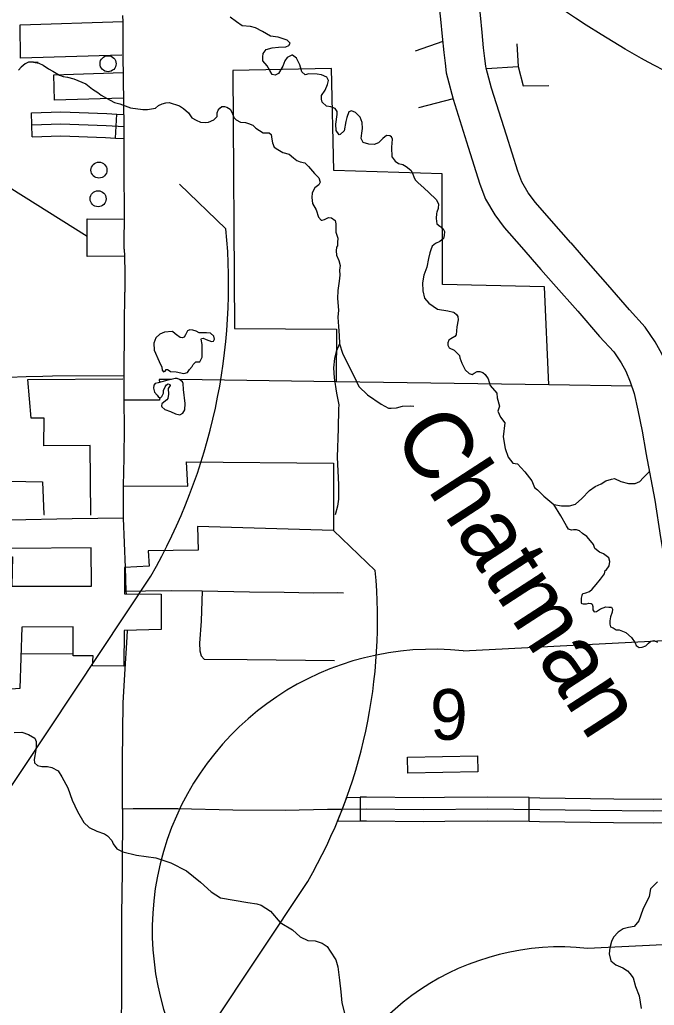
# Model space of a CAD drawing. Extents: x 22866 to 28196, y 1324810 to 1328105.
# Drawn here: x 25825.7 to 25920.9, y 1325934.5 to 1326082.4 of the extents above; entities that cross this region are included whole.
import ezdxf

# ---------------------------------------------------------------- set-up
doc = ezdxf.new("R2010")
doc.units = 0
for name, color, linetype in [('Level 10', 7, 'Continuous'), ('Level 31', 7, 'Continuous'), ('Level 32', 7, 'Continuous'), ('Level 33', 7, 'Continuous'), ('Level 35', 7, 'Continuous'), ('Level 5', 7, 'Continuous'), ('Level 56', 7, 'Continuous'), ('Level 6', 7, 'Continuous'), ('Level 63', 7, 'Continuous')]:
    doc.layers.add(name, color=color, linetype=linetype)

msp = doc.modelspace()

# ---------------------------------------------------------------- linework, layer by layer
at = {"layer": 'Level 10'}
for points in [[(25895.05, 1326080.47), (25894.8, 1326083.11), (25894.15, 1326088.91), (25893.68, 1326091.57)], [(25887.77, 1326090.53), (25888.21, 1326088.05), (25888.83, 1326082.49), (25889.08, 1326079.91)], [(25889.08, 1326079.91), (25889.31, 1326077.49), (25889.52, 1326075.88), (25889.67, 1326074.45), (25889.84, 1326073.68), (25890.71, 1326070.47), (25892.98, 1326063.3), (25894.73, 1326057.73), (25895.58, 1326055.48), (25896.94, 1326053.13), (25898.37, 1326051.22), (25900.96, 1326048.25), (25903.88, 1326044.94)], [(25908.38, 1326048.91), (25905.47, 1326052.21), (25903.04, 1326055), (25901.96, 1326056.44), (25901.02, 1326058.06), (25900.4, 1326059.69), (25898.7, 1326065.1), (25896.47, 1326072.16), (25895.67, 1326075.13), (25895.6, 1326075.44), (25895.48, 1326076.6), (25895.27, 1326078.17), (25895.05, 1326080.47)], [(25925.53, 1326018.46), (25924.97, 1326021.79), (25924.28, 1326025.05), (25923.67, 1326027.88), (25922.9, 1326030.2), (25922, 1326032.28), (25921.03, 1326034.05), (25919.52, 1326036.28), (25917.16, 1326038.87), (25913.93, 1326042.62), (25910.26, 1326046.76), (25908.39, 1326048.9)], [(25903.87, 1326044.94), (25905.76, 1326042.79), (25909.41, 1326038.67), (25912.67, 1326034.88), (25914.8, 1326032.55), (25915.91, 1326030.91), (25916.6, 1326029.64), (25917.28, 1326028.06), (25917.87, 1326026.3), (25918.41, 1326023.79), (25919.07, 1326020.67), (25919.61, 1326017.46)], [(25919.62, 1326017.41), (25920.95, 1326010.28), (25921.81, 1326004.72), (25922.47, 1326000.87), (25923.07, 1325997.99), (25924.25, 1325990.17), (25925.03, 1325984.11), (25925.3, 1325981.88), (25931.25, 1325982.7)]]:
    msp.add_lwpolyline(points, dxfattribs=at)
at = {"layer": 'Level 31'}
for p, q in [((25873.34, 1325962.08), (25874.74, 1325965.69)), ((25876.75, 1325965.7), (25876.77, 1325962.1)), ((25902.09, 1325962.05), (25902.12, 1325965.65))]:
    msp.add_line(p, q, dxfattribs=at)
for points in [[(25841.39, 1326046.91), (25841.44, 1326044.37), (25841.44, 1326041.53)], [(25841.39, 1326036.43), (25841.44, 1326041.53)], [(25841.36, 1326028.5), (25841.36, 1326028.97), (25841.39, 1326036.43)], [(25841.36, 1326028.97), (25830.62, 1326028.91), (25829.16, 1326028.87), (25826.66, 1326028.79), (25823.99, 1326028.73)], [(25841.67, 1325996.63), (25841.54, 1326000.2)], [(25841.67, 1325996.63), (25841.38, 1325996.61)], [(25841.67, 1325996.63), (25844.57, 1325996.71), (25848.49, 1325996.76), (25853.07, 1325996.68), (25860.18, 1325996.54), (25865.38, 1325996.47)], [(25841.71, 1325996.24), (25841.67, 1325996.63)], [(25853.07, 1325996.68), (25852.91, 1325992.14), (25852.66, 1325988.86), (25852.73, 1325987.71), (25852.91, 1325986.95), (25853.36, 1325986.43), (25859.82, 1325986.37), (25872.92, 1325986.23)], [(25865.38, 1325996.47), (25869.74, 1325996.4), (25873.38, 1325996.42), (25874.26, 1325996.38)], [(25841.11, 1325963.91), (25841.11, 1325971.2), (25841.22, 1325979.88), (25841.53, 1325984.99), (25841.77, 1325988.9), (25841.84, 1325990.73)], [(25825.88, 1325987.24), (25833.72, 1325987.27)], [(25874.74, 1325965.69), (25876.75, 1325965.7)], [(25889.42, 1325965.66), (25886.26, 1325965.64), (25877.69, 1325965.71), (25876.75, 1325965.7)], [(25902.12, 1325965.65), (25895.89, 1325965.71), (25889.42, 1325965.66)], [(25902.12, 1325965.65), (25903.72, 1325965.64), (25911.33, 1325965.5), (25914.8, 1325965.46)], [(25914.8, 1325965.46), (25920.74, 1325965.4), (25927.25, 1325965.47)], [(25874.07, 1325963.89), (25871.85, 1325963.87), (25865.53, 1325963.7), (25857.66, 1325963.77), (25849.4, 1325963.98), (25842.73, 1325963.98), (25841.11, 1325963.91)], [(25841.11, 1325963.91), (25841.04, 1325954.57), (25840.94, 1325948.06), (25840.94, 1325940.45), (25840.94, 1325936.85), (25840.91, 1325930.85), (25840.94, 1325926.9), (25840.91, 1325921.06)], [(25927.45, 1325963.67), (25920.74, 1325963.6), (25911.3, 1325963.7), (25903.7, 1325963.84), (25895.89, 1325963.91), (25886.26, 1325963.84), (25877.69, 1325963.91), (25874.07, 1325963.89)], [(25876.77, 1325962.1), (25873.34, 1325962.08)], [(25889.45, 1325962.06), (25886.26, 1325962.04), (25877.69, 1325962.11), (25876.77, 1325962.1)], [(25902.09, 1325962.05), (25895.89, 1325962.11), (25889.45, 1325962.06)], [(25914.76, 1325961.86), (25911.28, 1325961.9), (25903.67, 1325962.04), (25902.09, 1325962.05)], [(25927.84, 1325961.88), (25920.74, 1325961.8), (25914.76, 1325961.86)]]:
    msp.add_lwpolyline(points, dxfattribs=at)
at = {"layer": 'Level 32'}
for p, q in [((25827.56, 1326064.83), (25827.44, 1326068.43)), ((25840.07, 1326064.65), (25840.26, 1326068.25))]:
    msp.add_line(p, q, dxfattribs=at)
for points in [[(25827.44, 1326068.43), (25831.86, 1326068.57), (25838.74, 1326068.33), (25840.26, 1326068.25)], [(25840.26, 1326068.25), (25841.35, 1326068.19)], [(25827.5, 1326066.63), (25831.86, 1326066.77), (25838.66, 1326066.53), (25841.38, 1326066.39)], [(25827.56, 1326064.83), (25831.86, 1326064.97), (25838.58, 1326064.73), (25840.07, 1326064.65)], [(25840.07, 1326064.65), (25841.29, 1326064.59)]]:
    msp.add_lwpolyline(points, dxfattribs=at)
at = {"layer": 'Level 33'}
for points in [[(25910.68, 1326081.61), (25909.05, 1326082.66), (25907.69, 1326083.55), (25906.83, 1326084.36), (25905.86, 1326085.46), (25904.81, 1326086.82), (25903.74, 1326088.05), (25902.96, 1326088.91), (25902.07, 1326089.59), (25901.26, 1326090.06), (25900.32, 1326090.64), (25899.51, 1326091.11)], [(25841.21, 1326077.16), (25841.2, 1326082.07), (25841.17, 1326083.02)], [(25953.2, 1326070.87), (25945.13, 1326070.88), (25938.31, 1326070.9), (25936.09, 1326070.95), (25932.09, 1326071.31), (25928.56, 1326071.94), (25927.7, 1326072.15), (25925.88, 1326073.01), (25923.23, 1326074.32), (25919.98, 1326076.04), (25918.96, 1326076.57), (25916.5, 1326078), (25912.93, 1326080.21), (25910.68, 1326081.61)], [(25889.15, 1326079.16), (25885, 1326077.69)], [(25900.24, 1326078.77), (25900.48, 1326075.38), (25901.23, 1326072.5), (25905.08, 1326072.54)], [(25841.37, 1326047.99), (25841.39, 1326053.83), (25841.35, 1326059.21), (25841.38, 1326066.39), (25841.21, 1326077.16)], [(25895.69, 1326075.07), (25900.48, 1326075.38)], [(25890.69, 1326070.56), (25885.52, 1326069.2)], [(25841.37, 1326047.99), (25841.39, 1326046.91)], [(25841.39, 1326021.16), (25841.37, 1326025.27), (25841.36, 1326028.5)], [(25841.27, 1326012.45), (25841.34, 1326016.65), (25841.39, 1326021.16)], [(25841.24, 1326007.61), (25841.27, 1326012.45)], [(25841.24, 1326007.61), (25833.55, 1326007.52), (25824.33, 1326007.28)], [(25841.54, 1326000.2), (25841.24, 1326007.61)]]:
    msp.add_lwpolyline(points, dxfattribs=at)
at = {"layer": 'Level 35'}
for points in [[(25869.06, 1326074.31), (25868.49, 1326074.13), (25868.02, 1326074.6), (25867.7, 1326075.65), (25867.23, 1326076.64), (25866.6, 1326077.11), (25866.5, 1326077.11), (25865.82, 1326076.75), (25865.45, 1326076.23), (25865.14, 1326075.44), (25864.51, 1326074.34), (25863.99, 1326074.08), (25863.57, 1326074.18), (25863.21, 1326074.81), (25862.79, 1326075.49), (25862.16, 1326076.23), (25862.16, 1326076.85), (25862.21, 1326077.32), (25862.68, 1326077.95), (25863.57, 1326078.21), (25864.51, 1326078.27), (25865.61, 1326078.32), (25866.08, 1326078.53), (25866.24, 1326078.89), (25865.82, 1326079.36), (25864.46, 1326079.78), (25863.31, 1326079.94), (25862.11, 1326080.62), (25861.06, 1326081.2), (25860.33, 1326081.41), (25859.08, 1326081.51), (25858.19, 1326082.09), (25857.25, 1326082.77)], [(25828.44, 1326075.98), (25827.76, 1326076.03), (25827.03, 1326076.06), (25826.51, 1326075.77), (25825.93, 1326075.27), (25825.49, 1326074.86)], [(25827.76, 1326076.03), (25828.57, 1326075.9), (25829.19, 1326075.61), (25830, 1326075.04), (25830.68, 1326074.67), (25831.65, 1326074.1), (25832.22, 1326073.89), (25832.88, 1326073.78), (25833.81, 1326073.55), (25835.59, 1326072.79), (25836.61, 1326072), (25837.39, 1326071.48), (25837.92, 1326071.09), (25838.7, 1326070.64), (25839.9, 1326069.99), (25840.71, 1326069.81)], [(25871.99, 1326073.29), (25871.78, 1326073.77), (25870.94, 1326074.13), (25870.32, 1326074.24), (25869.06, 1326074.31)], [(25881.56, 1326061.78), (25881.5, 1326063.3), (25881.61, 1326064.5), (25881.45, 1326064.82), (25881.19, 1326064.98), (25880.72, 1326065.03), (25880.14, 1326064.56), (25879.52, 1326063.93), (25878.84, 1326063.67), (25878.05, 1326063.72), (25877.22, 1326063.98), (25876.9, 1326064.56), (25877.01, 1326065.39), (25877.11, 1326066.07), (25877.06, 1326066.96), (25876.75, 1326067.8), (25876.07, 1326068.48), (25875.44, 1326068.74), (25875.07, 1326068.59), (25874.76, 1326067.75), (25874.6, 1326067.12), (25874.34, 1326065.71), (25873.77, 1326065.18), (25873.61, 1326065.13), (25873.14, 1326065.76), (25873.09, 1326066.75), (25873.3, 1326068.17), (25873.3, 1326068.64), (25873.03, 1326069.06), (25872.35, 1326069.32), (25871.73, 1326069.42), (25871.05, 1326070.05), (25870.94, 1326070.47), (25870.94, 1326071.04), (25871.52, 1326071.83), (25871.88, 1326072.67), (25871.99, 1326073.29)], [(25840.71, 1326069.81), (25842.31, 1326069.18), (25844.14, 1326068.92), (25844.87, 1326068.94), (25846.07, 1326069.15), (25846.52, 1326069.55), (25847.07, 1326069.81), (25847.59, 1326069.96), (25848.11, 1326069.99), (25849.65, 1326069.47), (25850.25, 1326069.08), (25851.03, 1326068.43), (25851.53, 1326067.67), (25852.16, 1326067.33), (25852.81, 1326067.02), (25853.6, 1326066.96), (25854.01, 1326067.04), (25854.82, 1326067.36), (25855.29, 1326067.9), (25855.32, 1326068.43), (25855.45, 1326068.82), (25855.69, 1326069.16), (25856, 1326069.37), (25856.42, 1326069.4), (25856.78, 1326069.29), (25857.25, 1326068.98), (25857.54, 1326068.43), (25857.8, 1326067.75), (25858.14, 1326067.36), (25858.8, 1326067.04), (25859.55, 1326066.96), (25860, 1326066.81), (25860.65, 1326066.6), (25861.1, 1326066.13), (25862.22, 1326065.42), (25862.74, 1326065.45), (25863.11, 1326065.45), (25863.42, 1326065.18), (25863.5, 1326064.5), (25863.63, 1326063.95), (25863.87, 1326063.27), (25864.39, 1326062.91), (25865.17, 1326062.49), (25866.09, 1326062.25), (25866.77, 1326061.7), (25867.27, 1326061.29), (25867.76, 1326061.08), (25868.44, 1326060.92), (25869.02, 1326060.4), (25869.93, 1326059.35)], [(25881.56, 1326061.78), (25882.03, 1326061.18), (25882.53, 1326060.82), (25883.16, 1326060.68), (25883.68, 1326060.4), (25884.36, 1326059.85), (25884.62, 1326059.38), (25884.86, 1326058.67), (25885.07, 1326058.33), (25885.43, 1326057.96), (25886.37, 1326057.15), (25887.05, 1326056.5), (25888.18, 1326055.43), (25888.49, 1326054.8), (25888.44, 1326054.09), (25888.28, 1326053.52), (25888.23, 1326053.31), (25888.18, 1326052.6), (25888.26, 1326051.79), (25888.73, 1326051.42), (25888.99, 1326051.21), (25889.22, 1326051.03), (25889.41, 1326050.61), (25889.38, 1326050.04), (25889.28, 1326049.59), (25888.7, 1326049.11), (25888.05, 1326048.8)], [(25869.93, 1326059.35), (25870.56, 1326058.66), (25870.74, 1326058.05), (25870.56, 1326057.64), (25869.98, 1326057.19), (25869.57, 1326056.41), (25869.49, 1326055.75), (25869.62, 1326054.84), (25870.17, 1326053.89), (25870.51, 1326052.77), (25870.9, 1326052.35), (25871.06, 1326052.33), (25871.4, 1326052.43), (25872.02, 1326052.72), (25872.44, 1326052.69), (25872.99, 1326052.3), (25873.12, 1326051.75), (25873.09, 1326050.52), (25873.41, 1326049.6), (25873.38, 1326048.98), (25873.38, 1326048.45), (25873.23, 1326048.25), (25873.15, 1326047.7), (25873.23, 1326047.08), (25873.54, 1326046.27), (25873.75, 1326045.51), (25873.67, 1326044.83), (25873.72, 1326044.07), (25873.62, 1326043.15), (25873.43, 1326041.79), (25873.36, 1326040.56), (25873.51, 1326038.84), (25873.43, 1326037.79), (25873.49, 1326036.38)], [(25888.05, 1326048.8), (25887.55, 1326048.41), (25887.34, 1326047.88), (25887.21, 1326047.41), (25887.03, 1326046.57), (25886.74, 1326045.29), (25886.32, 1326044.09), (25886.11, 1326042.94), (25886.16, 1326041.73), (25886.4, 1326040.64), (25887.05, 1326039.85), (25888.36, 1326038.96), (25889.93, 1326038.73), (25890.74, 1326038.52), (25890.84, 1326038.49), (25891.21, 1326038.15), (25891.39, 1326037.86), (25891.47, 1326037.39), (25891.26, 1326036.32), (25891.16, 1326035.12)], [(25848.57, 1326035.64), (25847.39, 1326035.51), (25846.69, 1326035.22), (25846.09, 1326034.65), (25845.82, 1326033.84), (25845.88, 1326032.79), (25846.61, 1326031.09), (25847.03, 1326030.25), (25847.08, 1326029.81), (25847.26, 1326029.57), (25847.52, 1326029.68), (25847.68, 1326029.91), (25847.86, 1326029.91), (25847.97, 1326029.86), (25848.33, 1326029.6), (25849.14, 1326029.57), (25850.32, 1326029.31), (25850.84, 1326029.47), (25851.16, 1326029.89), (25851.55, 1326030.38), (25851.73, 1326030.64), (25852.12, 1326031.04), (25852.7, 1326031.06), (25853.06, 1326031.77), (25853.06, 1326033.65), (25852.93, 1326034.44), (25852.96, 1326034.57), (25853.2, 1326034.6), (25853.67, 1326034.41), (25854.45, 1326034.12), (25854.76, 1326034.15), (25854.89, 1326034.44), (25854.79, 1326034.91), (25854.29, 1326035.38), (25853.72, 1326035.43), (25853.06, 1326035.41), (25852.62, 1326035.41), (25852.15, 1326035.69), (25851.65, 1326035.82), (25851.21, 1326035.85), (25850.87, 1326035.72), (25850.58, 1326035.12), (25850.37, 1326034.75), (25850.06, 1326034.65), (25849.75, 1326034.73), (25849.2, 1326035.14), (25849.01, 1326035.25), (25848.59, 1326035.64)], [(25873.49, 1326036.38), (25873.62, 1326035.04), (25873.64, 1326033.78), (25874.11, 1326032.37), (25875.16, 1326030.22), (25875.89, 1326028.76), (25876.57, 1326027.37), (25877.85, 1326026.09), (25879.92, 1326024.7), (25880.99, 1326024.1), (25881.43, 1326024.1), (25882.22, 1326024.15), (25883.13, 1326024.42), (25884.33, 1326024.45), (25884.79, 1326024.43)], [(25891.16, 1326035.12), (25890.97, 1326034.87), (25890.37, 1326034.53), (25890.06, 1326034.29), (25889.93, 1326033.93), (25889.9, 1326033.58), (25890.13, 1326033.17), (25890.84, 1326032.83), (25891.65, 1326032.02), (25891.73, 1326031.65), (25892.02, 1326030.86), (25892.51, 1326029.87), (25893.09, 1326029.32), (25893.56, 1326029.14), (25893.87, 1326029.35), (25894.29, 1326029.63), (25894.71, 1326029.61), (25895.18, 1326029.48), (25895.52, 1326029.16), (25895.94, 1326028.51), (25896.25, 1326027.52), (25897.27, 1326026.36), (25897.32, 1326025.66), (25897.64, 1326024.43)], [(25873.64, 1326033.78), (25873.15, 1326032.6), (25872.91, 1326031.55), (25872.78, 1326030.17), (25872.84, 1326028.65), (25873.2, 1326026.35), (25873.57, 1326024.62), (25873.52, 1326023.99), (25873.44, 1326021.06), (25873.33, 1326016.74), (25873.49, 1326012.61), (25873.52, 1326010.46), (25873.36, 1326009.38), (25873.02, 1326008.12)], [(25848.33, 1326023.59), (25849.04, 1326023.28), (25849.69, 1326023.12), (25850.16, 1326023.36), (25850.45, 1326023.88), (25850.5, 1326024.82), (25850.27, 1326026.91), (25850.19, 1326027.83), (25850.11, 1326028.04), (25849.64, 1326028.43), (25849.33, 1326028.54), (25848.99, 1326028.54), (25847.55, 1326028.2), (25846.45, 1326027.91), (25846.03, 1326027.83), (25845.82, 1326027.57), (25845.75, 1326027.12), (25845.93, 1326026.52)], [(25845.93, 1326026.52), (25846.29, 1326026.08), (25846.53, 1326025.74), (25846.79, 1326025.66), (25847, 1326025.84), (25847.26, 1326026.34), (25847.26, 1326026.78), (25847.5, 1326027.31), (25847.71, 1326027.62), (25847.97, 1326027.75), (25848.2, 1326027.67), (25848.26, 1326027.49), (25847.97, 1326027.04), (25847.99, 1326026.23), (25847.89, 1326025.55), (25847.78, 1326025.37), (25847.31, 1326025.03), (25847, 1326024.74), (25846.97, 1326024.48), (25847.03, 1326024.3), (25847.47, 1326023.91), (25848.33, 1326023.59)], [(25897.64, 1326024.43), (25897.4, 1326023.67), (25897.82, 1326022.78), (25898.45, 1326021.89), (25898.19, 1326019.79), (25898.5, 1326018.07), (25898.97, 1326016.76), (25899.65, 1326015.87), (25900.38, 1326015.77), (25901.48, 1326014.56), (25902.53, 1326013.2), (25902.89, 1326012.21), (25903.36, 1326011.84), (25904.3, 1326010.9), (25905.82, 1326009.64), (25906.97, 1326009.43), (25908.17, 1326009.43), (25909.06, 1326009.7), (25910, 1326010.53), (25911.15, 1326011.74), (25911.99, 1326012.36), (25912.93, 1326012.73), (25913.61, 1326013.2), (25914.45, 1326013.46), (25914.92, 1326013.57), (25915.86, 1326013.1), (25917.01, 1326012.78), (25918, 1326012.78), (25918.73, 1326013.1), (25919.2, 1326013.67), (25920.14, 1326014.61)], [(25907.99, 1326005.96), (25907.71, 1326006.47), (25906.84, 1326007.93), (25905.82, 1326009.64)], [(25910.04, 1325996.12), (25910.23, 1325996.3), (25910.6, 1325996.4), (25911.15, 1325996.58), (25911.56, 1325996.92), (25912.14, 1325997.63), (25912.82, 1325998.42), (25913.39, 1325999.23), (25913.5, 1325999.75), (25913.68, 1325999.8), (25914.1, 1326000.46), (25914.23, 1326001.08), (25914.05, 1326001.66), (25913.24, 1326002.26), (25912.66, 1326002.52), (25911.96, 1326003.07), (25911.75, 1326003.65), (25911.33, 1326004.2), (25910.75, 1326004.83), (25910.1, 1326005.32), (25909.66, 1326005.71), (25909.21, 1326005.85), (25908.74, 1326005.85), (25908.45, 1326005.82), (25907.99, 1326005.96)], [(25910.04, 1325996.12), (25910.02, 1325996), (25909.92, 1325995.58), (25909.89, 1325995.21), (25909.89, 1325995), (25909.89, 1325994.85), (25909.99, 1325994.79), (25910.23, 1325994.72), (25910.7, 1325994.72), (25911.07, 1325994.82), (25911.43, 1325994.79), (25911.56, 1325994.69), (25911.67, 1325994.35), (25911.64, 1325994.04), (25911.64, 1325993.83), (25911.85, 1325993.54), (25912.19, 1325993.59), (25912.79, 1325994.01), (25913.6, 1325994.27), (25914.05, 1325994.22), (25914.46, 1325994.22), (25914.62, 1325993.96), (25914.57, 1325993.51), (25914.31, 1325992.78), (25914.2, 1325992.2), (25914.2, 1325991.68), (25914.33, 1325991.31), (25914.73, 1325991.13), (25915.17, 1325990.84), (25915.59, 1325990.82), (25916.63, 1325990.42), (25917.47, 1325989.69), (25918.02, 1325988.88), (25918.18, 1325988.49), (25918.59, 1325988.17), (25919.04, 1325988.23), (25919.59, 1325988.44), (25920.01, 1325988.83), (25920.34, 1325989.14)], [(25920.34, 1325989.14), (25920.81, 1325989.25), (25921.34, 1325988.99)], [(25824.88, 1325975.43), (25826.01, 1325975.48), (25827, 1325975.11), (25827.94, 1325974.56), (25828.18, 1325974.09), (25828.18, 1325973.13), (25827.97, 1325971.92), (25827.84, 1325971.37), (25827.92, 1325970.88), (25828.36, 1325970.48), (25828.99, 1325970.33), (25829.88, 1325970.33), (25830.53, 1325970.17), (25831.44, 1325969.67), (25832.02, 1325968.76), (25832.93, 1325967.13), (25833.54, 1325965.28), (25834.34, 1325963.56), (25835.31, 1325961.91), (25836.09, 1325961.16), (25837.24, 1325960.61), (25838.42, 1325960.21), (25838.86, 1325959.93), (25839.49, 1325959.22), (25839.7, 1325958.72), (25840.25, 1325957.96), (25841.16, 1325957.52), (25843.2, 1325957.02), (25846.1, 1325956.63), (25848.37, 1325955.85), (25850.69, 1325954.67), (25852.79, 1325952.97), (25854.41, 1325951.53), (25855.79, 1325950.64), (25859.9, 1325949.91), (25861.28, 1325949.7), (25861.93, 1325949.51), (25863.29, 1325948.59), (25864.75, 1325946.89), (25866.61, 1325945.79), (25867.78, 1325944.75), (25868.93, 1325944.2), (25870.03, 1325944.14), (25871.08, 1325943.8), (25871.81, 1325943.31), (25872.28, 1325942.6), (25873.09, 1325941.32), (25873.43, 1325940.27), (25873.64, 1325938.26), (25873.87, 1325936.5), (25874.03, 1325934.85), (25874.5, 1325932.91)], [(25921.37, 1325953.02), (25920.32, 1325951.98), (25920.11, 1325950.83), (25919.17, 1325948.84), (25918.54, 1325947.16), (25917.86, 1325946.33), (25917.03, 1325946.17), (25916.19, 1325945.96), (25915.46, 1325945.44), (25914.78, 1325944.7), (25914.47, 1325944.08), (25914.2, 1325943.13), (25914.1, 1325942.19), (25914.36, 1325941.14), (25915.09, 1325940.57), (25916.14, 1325940.1), (25916.87, 1325939.68), (25917.19, 1325939.26), (25917.71, 1325938.63), (25918.07, 1325937.32), (25918.6, 1325935.91), (25918.91, 1325934.03)]]:
    msp.add_lwpolyline(points, dxfattribs=at)
at = {"layer": 'Level 5'}
msp.add_lwpolyline([(25905.06, 1326027.59), (25873.15, 1326028.05)], dxfattribs=at)
at = {"layer": 'Level 56'}
msp.add_lwpolyline([(25883.92, 1325969.33), (25883.88, 1325971.73), (25894.38, 1325971.93), (25894.42, 1325969.53)], close=True, dxfattribs=at)
for centre in [(25838.94, 1326075.81), (25837.58, 1326059.83), (25837.45, 1326055.54)]:
    msp.add_circle(centre, 1.2, dxfattribs=at)
at = {"layer": 'Level 6'}
for points in [[(25841.01, 1326077.11), (25825.81, 1326076.65), (25825.78, 1326081.64), (25841.2, 1326082.14)], [(25917.5, 1326027.42), (25905.06, 1326027.59), (25904.41, 1326042.34), (25889.1, 1326042.65), (25889.05, 1326059.29), (25872.82, 1326059.78), (25872.46, 1326075.07), (25857.64, 1326074.81), (25857.89, 1326036.05), (25873.2, 1326035.98), (25873.15, 1326028.05), (25849.69, 1326028.39)], [(25841.22, 1326070.64), (25830.89, 1326070.35), (25830.8, 1326074.13), (25841.21, 1326074.47)], [(25841.43, 1326046.91), (25835.82, 1326046.88), (25835.82, 1326052.55), (25841.22, 1326052.49)], [(25836.37, 1326008.04), (25836.28, 1326018.51), (25829.32, 1326018.44), (25829.34, 1326022.62), (25827.43, 1326022.59), (25826.92, 1326028.41), (25841.14, 1326028.5)], [(25848.44, 1326028.41), (25846.63, 1326028.43), (25846.64, 1326027.96)], [(25846.66, 1326025.55), (25846.66, 1326025.33), (25841.37, 1326025.29)], [(25841.27, 1326012.47), (25850.92, 1326012.41), (25850.71, 1326016.07), (25872.74, 1326015.87), (25872.77, 1326005.77), (25852.37, 1326006.33), (25852.48, 1326002.82), (25844.95, 1326002.69), (25845.09, 1326000.39), (25841.41, 1326000.2), (25841.39, 1325996.25), (25846.89, 1325996.19), (25846.89, 1325990.89), (25841.36, 1325990.75), (25841.33, 1325985.41), (25836.62, 1325985.43)], [(25836.62, 1325985.43), (25836.69, 1325986.92), (25833.72, 1325986.92), (25833.69, 1325991.29), (25826.01, 1325991.26), (25825.7, 1325982.02), (25821.86, 1325981.71), (25821.77, 1325976.08), (25815.25, 1325976.02), (25809.44, 1325989.67), (25809.26, 1325997.41), (25820.97, 1325997.41), (25820.7, 1326002.1), (25824.59, 1326001.78), (25824.52, 1325997.4), (25836.46, 1325997.4), (25836.41, 1326003.14), (25824.47, 1326003.03), (25824.29, 1326008.28), (25824.13, 1326013.13), (25829.11, 1326013.07), (25829.29, 1326008.17), (25829.43, 1326008.16)]]:
    msp.add_lwpolyline(points, dxfattribs=at)
at = {"layer": 'Level 63'}
for p, q in [((25835.82, 1326049.88), (25813.34, 1326063.95)), ((25856.63, 1326051.04), (25849.66, 1326057.75)), ((25879.01, 1325999.76), (25872.77, 1326005.77)), ((25763.43, 1325875.59), (25845.35, 1325998.89)), ((25892.2, 1325987.67), (25948.69, 1325990.57)), ((25795.58, 1325842.7), (25868.91, 1325953.08)), ((25910.85, 1325943.04), (25961.42, 1325945.63))]:
    msp.add_line(p, q, dxfattribs=at)
for centre, radius, start, end in [((25769.1, 1326042.68), 87.93, 330.1335, 5.4564), ((25800.66, 1325992.27), 78.71, 330.1335, 5.4564), ((25979.55, 1325920.59), 76.48, 193.5839, 113.7904), ((25887.7, 1325945.79), 42.13, 83.8595, 243.6995), ((25906.82, 1325905.54), 37.71, 83.8595, 243.6995)]:
    msp.add_arc(centre, radius, start, end, dxfattribs=at)

# ---------------------------------------------------------------- texts
at = {"layer": 'Level 35'}
msp.add_text('Chatman', height=10.139, rotation=302.9427, dxfattribs=at).set_placement((25881.46, 1326020.09))
at = {"layer": 'Level 56'}
msp.add_text('9', height=7.6, dxfattribs=at).set_placement((25887.25, 1325974.34))

doc.saveas('drawing.dxf')
